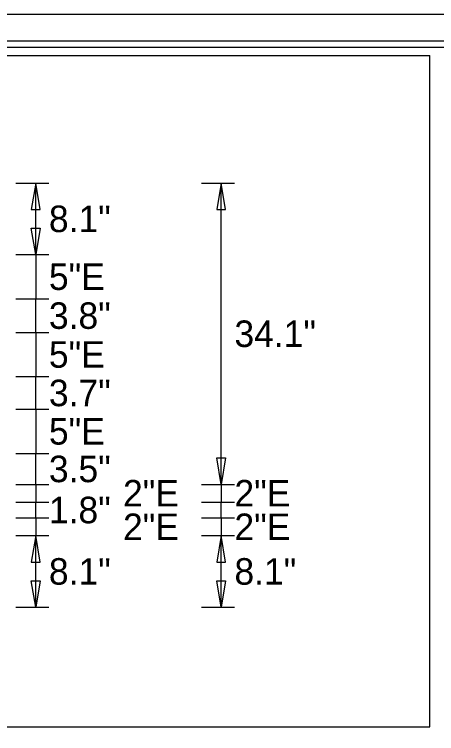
# Model space of a CAD drawing. Extents: x 17890628 to 17890844, y 17897693 to 17898031.
# Drawn here: x 17890758.2 to 17890772.14, y 17897976.07 to 17897999.81 of the extents above; entities that cross this region are included whole.
import ezdxf

# ---------------------------------------------------------------- set-up
doc = ezdxf.new("R2010")
doc.units = 0
for name, color, linetype in [('GSDims', 7, 'Continuous'), ('PlotBorder_dp', 7, 'Continuous'), ('SheetBorder_dp', 7, 'Continuous'), ('SheetLinesMisc2_dp', 7, 'Continuous')]:
    doc.layers.add(name, color=color, linetype=linetype)

msp = doc.modelspace()

# ---------------------------------------------------------------- linework, layer by layer
at = {"layer": 'GSDims'}
for p, q in [((17890758.247, 17897994.243), (17890759.34, 17897994.243)), ((17890758.903, 17897991.88), (17890758.903, 17897994.243)), ((17890764.372, 17897994.243), (17890765.465, 17897994.243)), ((17890765.028, 17897984.297), (17890765.028, 17897994.243)), ((17890758.247, 17897991.88), (17890759.34, 17897991.88)), ((17890758.247, 17897991.88), (17890759.34, 17897991.88)), ((17890758.903, 17897991.88), (17890758.903, 17897990.422)), ((17890758.247, 17897990.422), (17890759.34, 17897990.422)), ((17890758.247, 17897990.422), (17890759.34, 17897990.422)), ((17890758.903, 17897989.314), (17890758.903, 17897990.422)), ((17890758.247, 17897989.314), (17890759.34, 17897989.314)), ((17890758.247, 17897989.314), (17890759.34, 17897989.314)), ((17890758.903, 17897989.314), (17890758.903, 17897987.855)), ((17890758.247, 17897987.855), (17890759.34, 17897987.855)), ((17890758.247, 17897987.855), (17890759.34, 17897987.855)), ((17890758.903, 17897986.776), (17890758.903, 17897987.855)), ((17890758.247, 17897986.776), (17890759.34, 17897986.776)), ((17890758.247, 17897986.776), (17890759.34, 17897986.776)), ((17890758.903, 17897986.776), (17890758.903, 17897985.318)), ((17890758.247, 17897985.318), (17890759.34, 17897985.318)), ((17890758.247, 17897985.318), (17890759.34, 17897985.318)), ((17890758.903, 17897984.297), (17890758.903, 17897985.318)), ((17890758.247, 17897984.297), (17890759.34, 17897984.297)), ((17890758.247, 17897984.297), (17890759.34, 17897984.297)), ((17890758.903, 17897984.297), (17890758.903, 17897983.714)), ((17890764.372, 17897984.297), (17890765.465, 17897984.297)), ((17890764.372, 17897984.297), (17890765.465, 17897984.297)), ((17890765.028, 17897984.297), (17890765.028, 17897983.714)), ((17890758.247, 17897983.714), (17890759.34, 17897983.714)), ((17890758.247, 17897983.714), (17890759.34, 17897983.714)), ((17890758.903, 17897983.189), (17890758.903, 17897983.714)), ((17890764.372, 17897983.714), (17890765.465, 17897983.714)), ((17890764.372, 17897983.714), (17890765.465, 17897983.714)), ((17890765.028, 17897983.189), (17890765.028, 17897983.714)), ((17890758.247, 17897983.189), (17890759.34, 17897983.189)), ((17890758.247, 17897983.189), (17890759.34, 17897983.189)), ((17890758.903, 17897983.189), (17890758.903, 17897982.605)), ((17890764.372, 17897983.189), (17890765.465, 17897983.189)), ((17890764.372, 17897983.189), (17890765.465, 17897983.189)), ((17890765.028, 17897983.189), (17890765.028, 17897982.605)), ((17890758.247, 17897982.605), (17890759.34, 17897982.605)), ((17890758.247, 17897982.605), (17890759.34, 17897982.605)), ((17890758.903, 17897980.243), (17890758.903, 17897982.605)), ((17890764.372, 17897982.605), (17890765.465, 17897982.605)), ((17890764.372, 17897982.605), (17890765.465, 17897982.605)), ((17890765.028, 17897980.243), (17890765.028, 17897982.605)), ((17890758.247, 17897980.243), (17890759.34, 17897980.243)), ((17890764.372, 17897980.243), (17890765.465, 17897980.243))]:
    msp.add_line(p, q, dxfattribs=at)
for points in [[(17890758.903, 17897994.243), (17890758.757, 17897993.368), (17890759.049, 17897993.368)], [(17890765.028, 17897994.243), (17890764.882, 17897993.368), (17890765.174, 17897993.368)], [(17890758.903, 17897991.88), (17890758.757, 17897992.755), (17890759.049, 17897992.755)], [(17890765.028, 17897984.297), (17890764.882, 17897985.172), (17890765.174, 17897985.172)], [(17890758.903, 17897982.605), (17890758.757, 17897981.73), (17890759.049, 17897981.73)], [(17890765.028, 17897982.605), (17890764.882, 17897981.73), (17890765.174, 17897981.73)], [(17890758.903, 17897980.243), (17890758.757, 17897981.118), (17890759.049, 17897981.118)], [(17890765.028, 17897980.243), (17890764.882, 17897981.118), (17890765.174, 17897981.118)]]:
    msp.add_lwpolyline(points, close=True, dxfattribs=at)
at = {"layer": 'PlotBorder_dp'}
msp.add_lwpolyline([(17890700.471, 17897907.61), (17890843.989, 17897907.61), (17890843.989, 17897999.809), (17890700.471, 17897999.809)], close=True, dxfattribs=at)
at = {"layer": 'SheetBorder_dp'}
msp.add_line((17890705.254, 17897998.94), (17890839.205, 17897998.94), dxfattribs=at)
at = {"layer": 'SheetLinesMisc2_dp'}
for p, q in [((17890705.5, 17897998.732), (17890839.233, 17897998.732)), ((17890726.429, 17897998.455), (17890771.912, 17897998.455)), ((17890771.912, 17897976.3), (17890771.912, 17897998.455)), ((17890726.429, 17897976.3), (17890771.912, 17897976.3))]:
    msp.add_line(p, q, dxfattribs=at)

# ---------------------------------------------------------------- texts
at = {"layer": 'GSDims'}
for s, p in [('8.1"', (17890759.34, 17897992.624)), ('5"E', (17890759.34, 17897990.714)), ('3.8"', (17890759.34, 17897989.43)), ('34.1"', (17890765.465, 17897988.832)), ('5"E', (17890759.34, 17897988.147)), ('3.7"', (17890759.34, 17897986.878)), ('5"E', (17890759.34, 17897985.61)), ('3.5"', (17890759.34, 17897984.37)), ('2"E', (17890761.787, 17897983.568)), ('2"E', (17890765.465, 17897983.568)), ('1.8"', (17890759.34, 17897983.014)), ('2"E', (17890761.787, 17897982.46)), ('2"E', (17890765.465, 17897982.46)), ('8.1"', (17890759.34, 17897980.987)), ('8.1"', (17890765.465, 17897980.987))]:
    msp.add_text(s, height=0.875, dxfattribs=at).set_placement(p)

doc.saveas('drawing.dxf')
